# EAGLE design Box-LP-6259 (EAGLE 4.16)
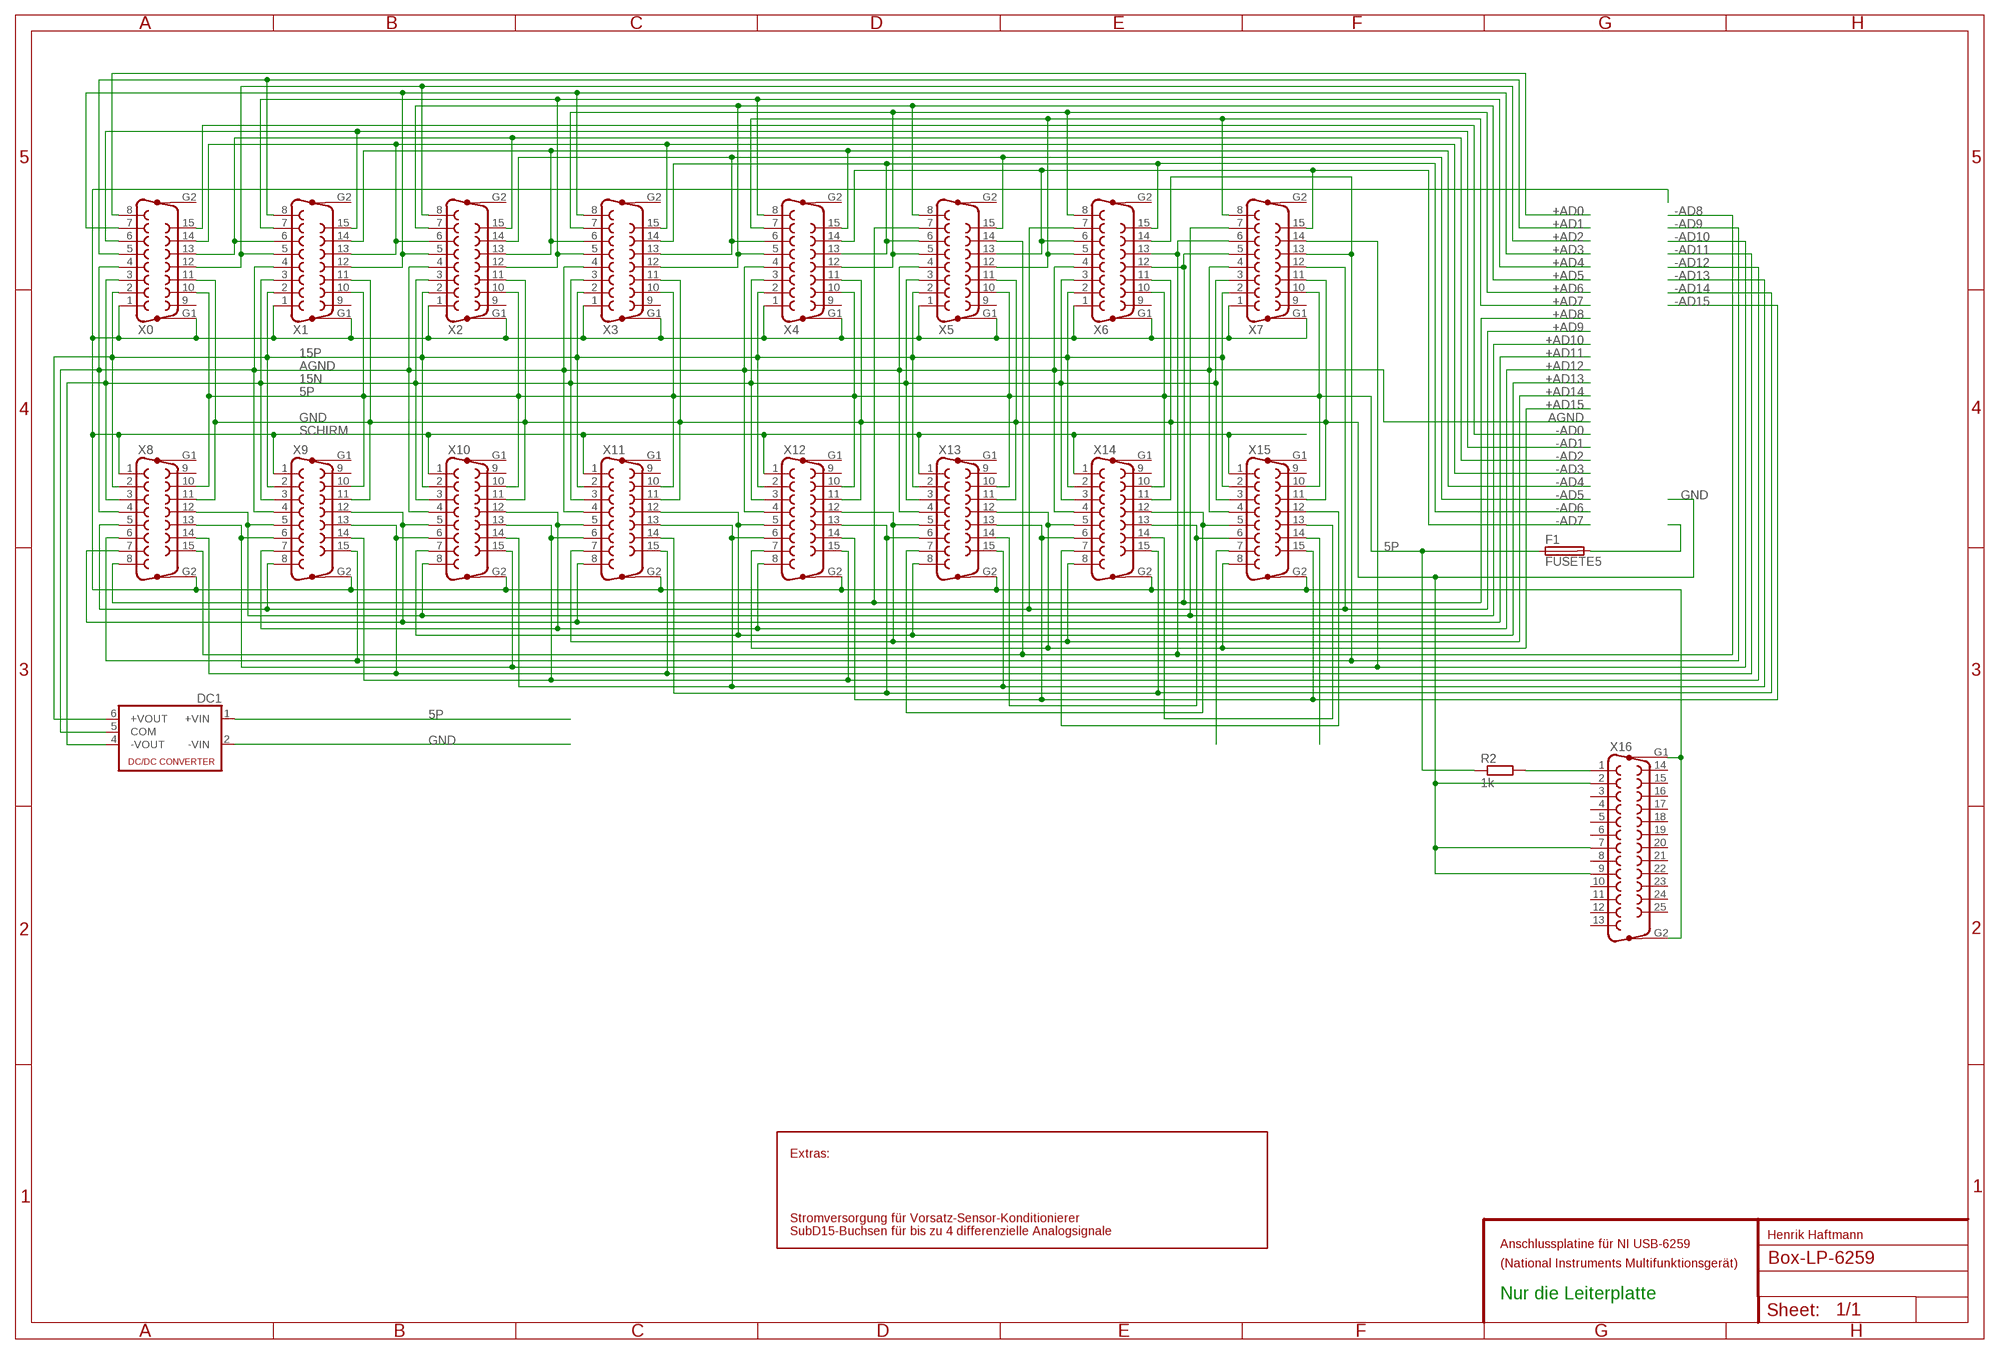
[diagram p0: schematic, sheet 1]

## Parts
DC1  NMA  [NMA]
F1  FUSETE5  [TE5]
R2  1k  R-EU_R0805  [R0805]
X0  F15VP  [F15VP]
X1  F15VP  [F15VP]
X2  F15VP  [F15VP]
X3  F15VP  [F15VP]
X4  F15VP  [F15VP]
X5  F15VP  [F15VP]
X6  F15VP  [F15VP]
X7  F15VP  [F15VP]
X8  F15VP  [F15VP]
X9  F15VP  [F15VP]
X10  F15VP  [F15VP]
X11  F15VP  [F15VP]
X12  F15VP  [F15VP]
X13  F15VP  [F15VP]
X14  F15VP  [F15VP]
X15  F15VP  [F15VP]
X16  F25VP  [F25VP]

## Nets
5P: DC1.1(+VIN) F1.1 R2.1 X0.10 X1.10 X2.10 X3.10 X4.10 X5.10 X6.10 X7.10 X8.10 X9.10 X10.10 X11.10 X12.10 X13.10 X14.10 X15.10
15N: DC1.4(-VOUT) X0.3 X1.3 X2.3 X3.3 X4.3 X5.3 X6.3 X7.3 X8.3 X9.3 X10.3 X11.3 X12.3 X13.3 X14.3 X15.3
15P: DC1.6(+VOUT) X0.2 X1.2 X2.2 X3.2 X4.2 X5.2 X6.2 X7.2 X8.2 X9.2 X10.2 X11.2 X12.2 X13.2 X14.2 X15.2
+AD0: X0.8
+AD1: X0.5 X1.8
+AD2: X0.12 X1.5 X2.8
+AD3: X0.7 X1.12 X2.5 X3.8
+AD4: X1.7 X2.12 X3.5 X4.8
+AD5: X2.7 X3.12 X4.5 X5.8
+AD6: X3.7 X4.12 X5.5 X6.8
+AD7: X4.7 X5.12 X6.5 X7.8
+AD8: X5.7 X6.12 X7.5 X8.8
+AD9: X6.7 X7.12 X8.5 X9.8
+AD10: X7.7 X8.12 X9.5 X10.8
+AD11: X8.7 X9.12 X10.5 X11.8
+AD12: X9.7 X10.12 X11.5 X12.8
+AD13: X10.7 X11.12 X12.5 X13.8
+AD14: X11.7 X12.12 X13.5 X14.8
+AD15: X12.7 X13.12 X14.5 X15.8
+AD16: X13.7 X14.12 X15.5
+AD17: X14.7 X15.12
+AD18: X15.7
-AD0: X0.15
-AD1: X0.6 X1.15
-AD2: X0.13 X1.6 X2.15
-AD3: X0.14 X1.13 X2.6 X3.15
-AD4: X1.14 X2.13 X3.6 X4.15
-AD5: X2.14 X3.13 X4.6 X5.15
-AD6: X3.14 X4.13 X5.6 X6.15
-AD7: X4.14 X5.13 X6.6 X7.15
-AD8: X5.14 X6.13 X7.6 X8.15
-AD9: X6.14 X7.13 X8.6 X9.15
-AD10: X7.14 X8.13 X9.6 X10.15
-AD11: X8.14 X9.13 X10.6 X11.15
-AD12: X9.14 X10.13 X11.6 X12.15
-AD13: X10.14 X11.13 X12.6 X13.15
-AD14: X11.14 X12.13 X13.6 X14.15
-AD15: X12.14 X13.13 X14.6 X15.15
-AD16: X13.14 X14.13 X15.6
-AD17: X14.14 X15.13
-AD18: X15.14
AGND: DC1.5(COM) X0.4 X1.4 X2.4 X3.4 X4.4 X5.4 X6.4 X7.4 X8.4 X9.4 X10.4 X11.4 X12.4 X13.4 X14.4 X15.4
GND: DC1.2(-VIN) X0.11 X1.11 X2.11 X3.11 X4.11 X5.11 X6.11 X7.11 X8.11 X9.11 X10.11 X11.11 X12.11 X13.11 X14.11 X15.11 X16.2 X16.7 X16.9
N$1: R2.2 X16.1
N$2: F1.2
SCHIRM: X0.1 X0.G1 X1.1 X1.G1 X2.1 X2.G1 X3.1 X3.G1 X4.1 X4.G1 X5.1 X5.G1 X6.1 X6.G1 X7.1 X7.G1 X8.1 X8.G2 X9.1 X9.G2 X10.1 X10.G2 X11.1 X11.G2 X12.1 X12.G2 X13.1 X13.G2 X14.1 X14.G2 X15.1 X15.G2 X16.G1 X16.G2
Unconnected: X0.9 X0.G2 X1.9 X1.G2 X2.9 X2.G2 X3.9 X3.G2 X4.9 X4.G2 X5.9 X5.G2 X6.9 X6.G2 X7.9 X7.G2 X8.9 X8.G1 X9.9 X9.G1 X10.9 X10.G1 X11.9 X11.G1 X12.9 X12.G1 X13.9 X13.G1 X14.9 X14.G1 X15.9 X15.G1 X16.3 X16.4 X16.5 X16.6 X16.8 X16.10 X16.11 X16.12 X16.13 X16.14 X16.15 X16.16 X16.17 X16.18 X16.19 X16.20 X16.21 X16.22 X16.23 X16.24 X16.25

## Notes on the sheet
- Extras:
- Stromversorgung für Vorsatz-Sensor-Konditionierer
- SubD15-Buchsen für bis zu 4 differenzielle Analogsignale
- Henrik Haftmann
- Anschlussplatine für NI USB-6259
- (National Instruments Multifunktionsgerät)
- Nur die Leiterplatte

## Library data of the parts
DC1 = dc-dc-converter:NMA: DC-DC CONVERTER
F1 = fuse:FUSE: Fuse
R2 = rcl:R-EU_: RESISTOR, European symbol
X0 X1-X15 = con-subd:F15VP: SUB-D
X16 = con-subd:F25VP: SUB-D

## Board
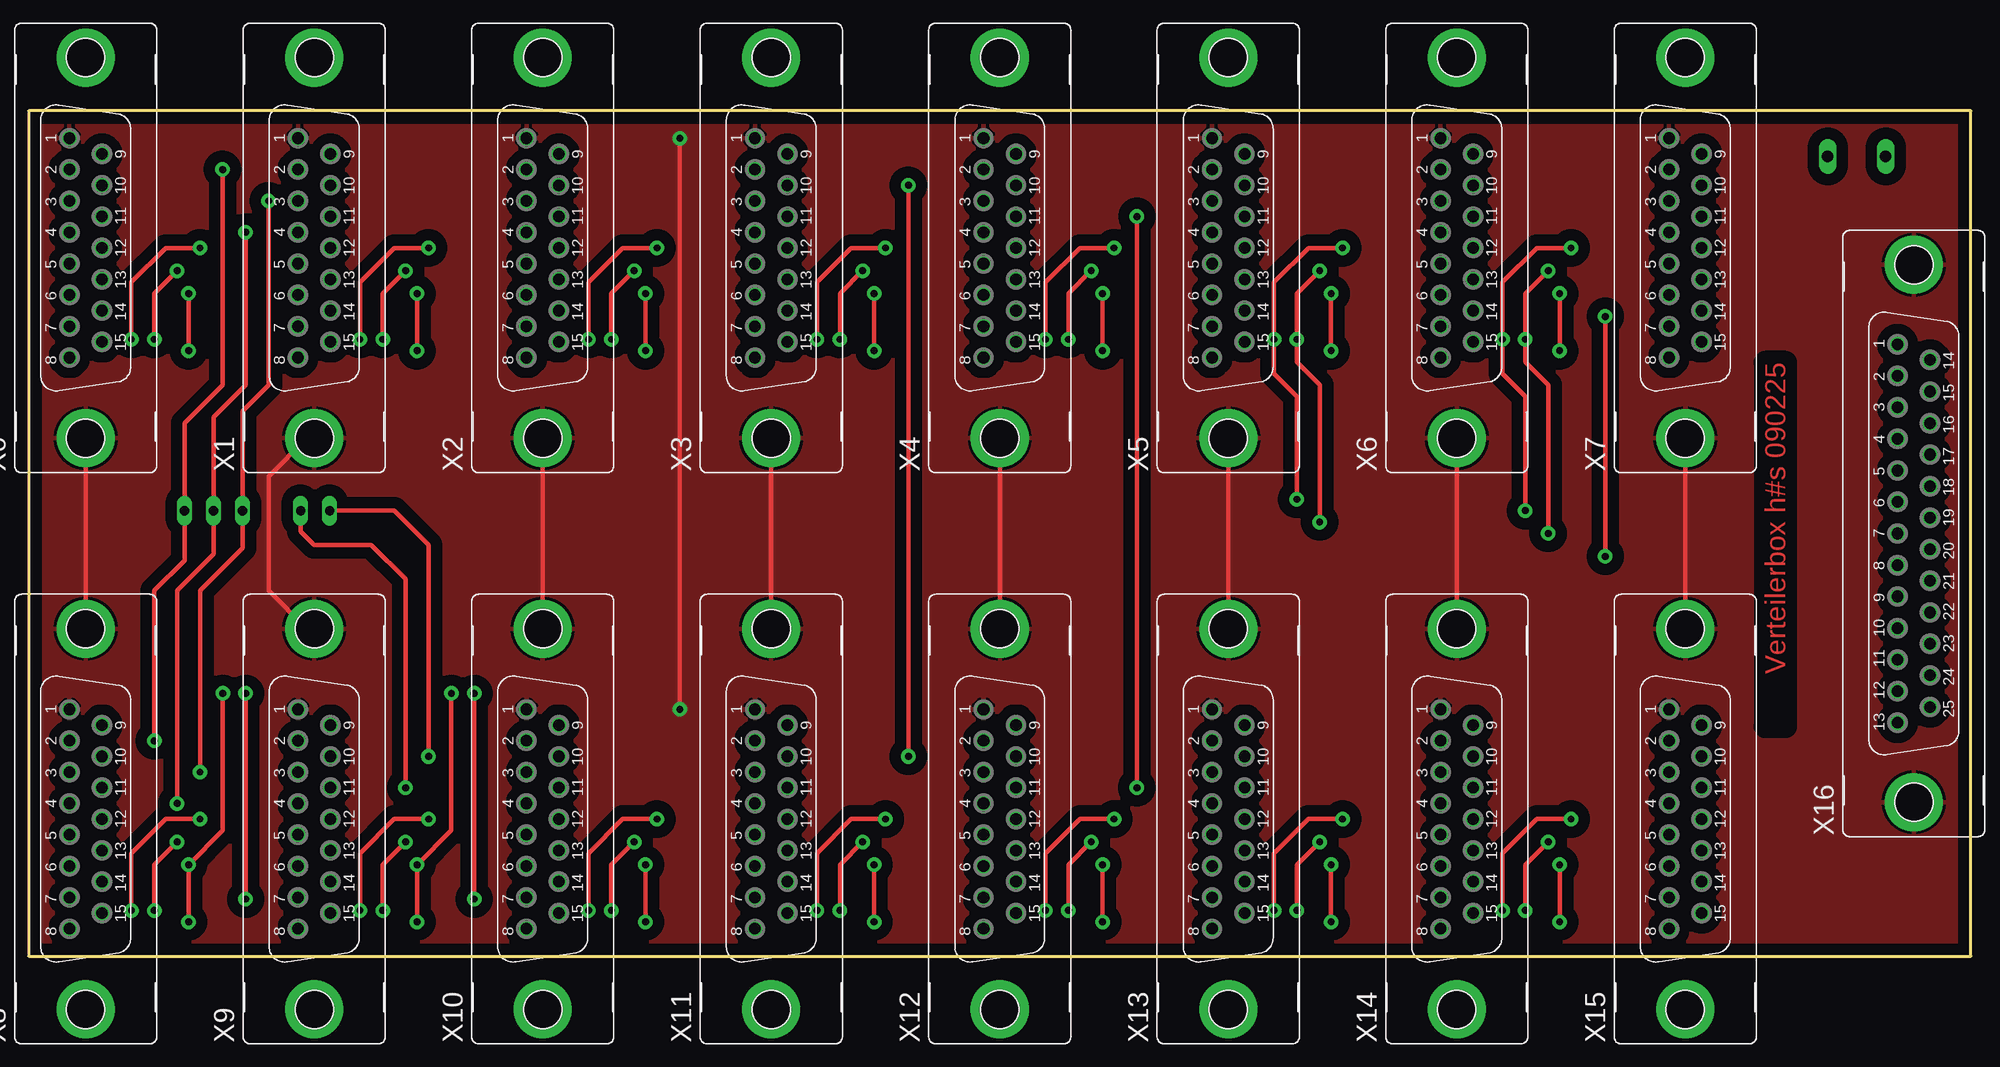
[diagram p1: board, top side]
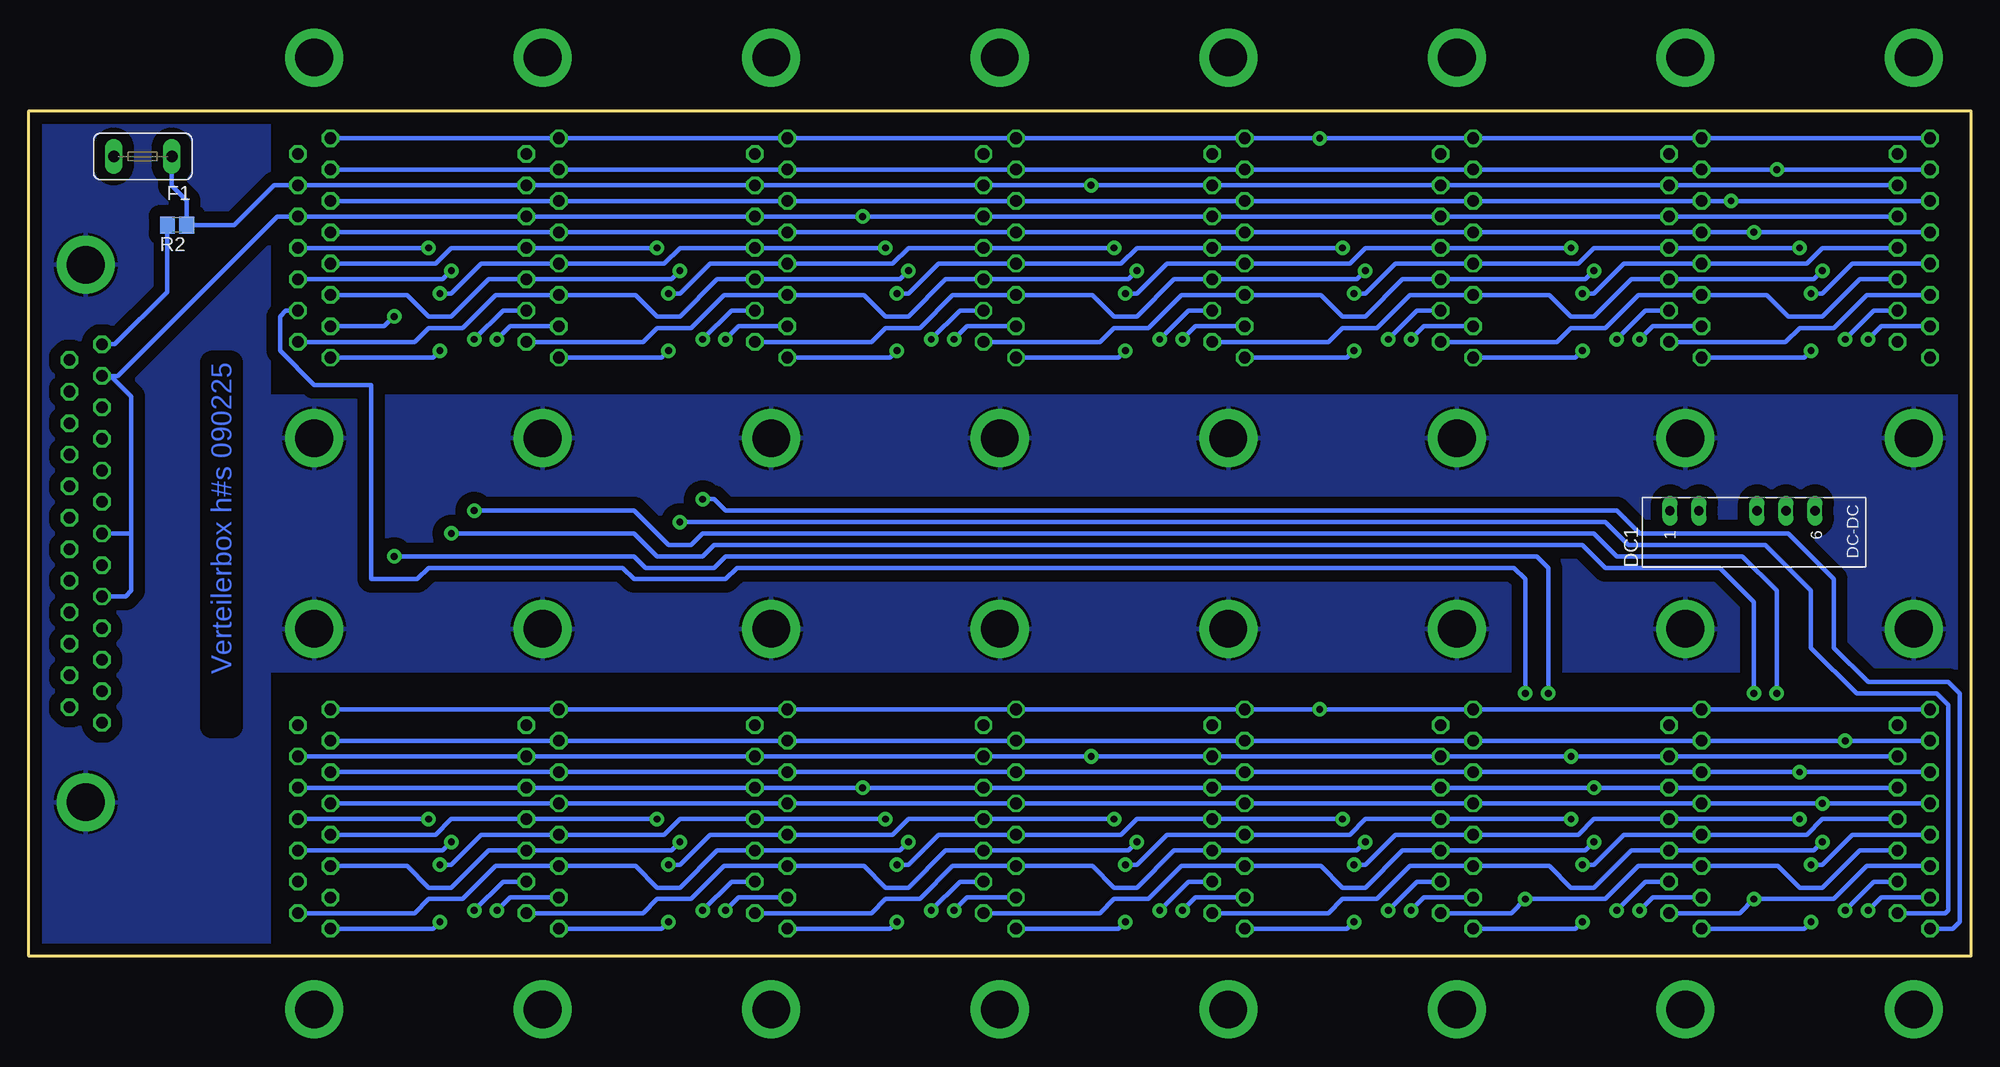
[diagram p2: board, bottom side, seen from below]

Size 170 x 74 mm. Coordinates in mm from the lower left corner, seen from the top.
Outline: 0,0 170,0 170,74 0,74 0,0
Copper layers (1*16): Top 0.035mm / dielectric 1.5mm / Bottom 0.035mm
Design rules "Felber": minimum track width 0.15mm, minimum drill 0.3mm, track to track 0.15mm, track to pad 0.15mm, pad to pad 0.15mm, via to via 0.15mm, smd to smd 0mil, copper to edge 0.3mm, drill to drill 0.3mm, minimum pad ring 10mil, minimum via ring 8mil, stop-mask expansion 4mil, vias tented up to drill 0mil, thermal gap 10mil

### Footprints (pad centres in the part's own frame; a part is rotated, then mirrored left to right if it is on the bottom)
NMA = drill 0.813 long: 1 0,6.35; 2 0,3.81; 4 0,-1.27; 5 0,-3.81; 6 0,-6.35
TE5 = drill 1.016 long: 1 -2.54,0; 2 2.54,0
R0805 = smd 1.3 x 1.5: 1 -0.85,0; 2 0.85,0
F15VP = drill 1.016 octagon: 1 9.601,1.422; 2 6.858,1.422; 3 4.115,1.422; 4 1.372,1.422; 5 -1.372,1.422; 6 -4.115,1.422; 7 -6.858,1.422; 8 -9.601,1.422; 9 8.23,-1.422; 10 5.486,-1.422; 11 2.743,-1.422; 12 0,-1.422; 13 -2.743,-1.422; 14 -5.486,-1.422; 15 -8.23,-1.422 | drill 3.302 pad 5.08 round: G1 -16.662,0; G2 16.662,0
F25VP = drill 1.016 octagon: 1 16.561,1.422; 2 13.792,1.422; 3 11.049,1.422; 4 8.28,1.422; 5 5.512,1.422; 6 2.769,1.422; 7 0,1.422; 8 -2.769,1.422; 9 -5.512,1.422; 10 -8.28,1.422; 11 -11.049,1.422; 12 -13.792,1.422; 13 -16.561,1.422; 14 15.189,-1.422; 15 12.421,-1.422; 16 9.652,-1.422; 17 6.909,-1.422; 18 4.14,-1.422; 19 1.372,-1.422; 20 -1.372,-1.422; 21 -4.14,-1.422; 22 -6.909,-1.422; 23 -9.652,-1.422; 24 -12.421,-1.422; 25 -15.189,-1.422 | drill 3.302 pad 5.08 round: G1 -23.52,0; G2 23.52,0

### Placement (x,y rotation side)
DC1  20,39 90 bottom
F1  160,70 180 bottom
R2  157,64 180 bottom
X0  5,62 90 top
X1  25,62 90 top
X2  45,62 90 top
X3  65,62 90 top
X4  85,62 90 top
X5  105,62 90 top
X6  125,62 90 top
X7  145,62 90 top
X8  5,12 90 top
X9  25,12 90 top
X10  45,12 90 top
X11  65,12 90 top
X12  85,12 90 top
X13  105,12 90 top
X14  125,12 90 top
X15  145,12 90 top
X16  165,37 90 top

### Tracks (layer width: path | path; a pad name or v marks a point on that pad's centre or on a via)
5P  (via drill 0.6 pad 1.27)
  Top 0.406: 77,36 v77,67.49 | 77,36 | v77,17.49 77,36 | DC1.1 32,39 35,36 v35,17.49
  Bottom 0.406: X0.10 X1.10 X2.10 X3.10 v77,67.49 X4.10 X5.10 X6.10 X7.10 148.51,67.49 152,64 R2.1 156.15,66.15 157.46,67.46 F1.1 | X8.10 X9.10 v35,17.49 X10.10 X11.10 v77,17.49 X12.10 X13.10 X14.10 X15.10
15N  (via drill 0.6 pad 1.27)
  Top 0.406: v21,66.11 21,50 18.73,47.73 DC1.4 18.73,35.73 15,32 v15,16.11
  Bottom 0.406: X0.3 v21,66.11 X1.3 X2.3 X3.3 X4.3 X5.3 X6.3 X7.3 | X8.3 v15,16.11 X9.3 X10.3 X11.3 X12.3 X13.3 X14.3 X15.3
15P  (via drill 0.6 pad 1.27)
  Top 0.406: v11,18.86 11,32 13.65,34.65 DC1.6 13.65,46.65 17,50 16.98,50.02 v16.98,68.86
  Bottom 0.406: X0.2 v16.98,68.86 X1.2 X2.2 X3.2 X4.2 X5.2 X6.2 X7.2 | X8.2 v11,18.86 X9.2 X10.2 X11.2 X12.2 X13.2 X14.2 X15.2
+AD1  (via drill 0.6 pad 1.27)
  Top 0.406: v14,58 v14,53
  Bottom 0.406: X0.5 10.37,60.63 13,58 v14,58 | X1.8 14.6,52.4 v14,53
+AD2  (via drill 0.6 pad 1.27)
  Top 0.406: v34,58 v34,53
  Bottom 0.406: X0.12 13,62 14.37,60.63 X1.5 30.37,60.63 33,58 v34,58 | X2.8 34.6,52.4 v34,53
+AD3  (via drill 0.6 pad 1.27)
  Top 0.406: v54,58 v54,53 | v9,54 9,59 12,62 v15,62
  Bottom 0.406: v54,58 53,58 50.37,60.63 X2.5 34.37,60.63 33,62 X1.12 v15,62 | X3.8 54.6,52.4 v54,53 | X0.7 7.86,55.14 v9,54
+AD4  (via drill 0.6 pad 1.27)
  Top 0.406: v74,58 v74,53 | v29,54 29,59 32,62 v35,62
  Bottom 0.406: v74,58 73,58 70.37,60.63 X3.5 54.37,60.63 53,62 X2.12 v35,62 | X4.8 74.6,52.4 v74,53 | X1.7 27.86,55.14 v29,54
+AD5  (via drill 0.6 pad 1.27)
  Top 0.406: v94,58 v94,53 | v55,62 52,62 49,59 v49,54
  Bottom 0.406: v94,58 93,58 90.37,60.63 X4.5 74.37,60.63 73,62 X3.12 v55,62 | X5.8 94.6,52.4 v94,53 | X2.7 47.86,55.14 v49,54
+AD6  (via drill 0.6 pad 1.27)
  Top 0.406: v114,58 v114,53 | v69,54 69,59 72,62 v75,62
  Bottom 0.406: v114,58 113,58 110.37,60.63 X5.5 94.37,60.63 93,62 X4.12 v75,62 | X6.8 114.6,52.4 v114,53 | X3.7 67.86,55.14 v69,54
+AD7  (via drill 0.6 pad 1.27)
  Top 0.406: v134,58 v134,53 | v89,54 89,59 92,62 v95,62
  Bottom 0.406: v134,58 133,58 130.37,60.63 X6.5 114.37,60.63 113,62 X5.12 v95,62 | X7.8 134.6,52.4 v134,53 | X4.7 87.86,55.14 v89,54
+AD8  (via drill 0.6 pad 1.27)
  Top 0.406: v115,62 112,62 109,59 v109,54 109,51 111,49 v111,40
  Bottom 0.406: X7.5 134.37,60.63 133,62 X6.12 v115,62 | X8.8 1.6,2.4 1,3 1,23 2,24 9,24 12,27 12,33 16,37 29,37 31,39 109,39 110,40 v111,40 | X5.7 107.86,55.14 v109,54
+AD9  (via drill 0.6 pad 1.27)
  Top 0.406: v14,3 v14,8 17,11 v17,23 | v131,39 131,49 129,51 v129,54 129,59 132,62 v135,62
  Bottom 0.406: X8.5 10.37,10.63 13,8 v14,8 | X9.8 14.6,2.4 v14,3 | v17,23 17,32 20,35 31,35 33,37 111,37 112,36 114,36 117,39 v131,39 | X6.7 127.86,55.14 v129,54 | v135,62 X7.12
+AD10  (via drill 0.6 pad 1.27)
  Top 0.406: v34,3 v34,8 37,11 v37,23 | v138,35 v138,56
  Bottom 0.406: v34,8 33,8 30.37,10.63 X9.5 14.37,10.63 13,12 X8.12 | X10.8 34.6,2.4 v34,3 | X7.7 138.86,55.14 v138,56 | v138,35 117,35 116,34 110,34 109,35 38,35 37,34 v37,23
+AD11  (via drill 0.6 pad 1.27)
  Top 0.406: v54,8 v54,3 | v9,4 9,9 12,12 v15,12
  Bottom 0.406: v54,8 53,8 50.37,10.63 X10.5 34.37,10.63 33,12 X9.12 v15,12 | X11.8 54.6,2.4 v54,3 | X8.7 7.86,5.14 v9,4
+AD12  (via drill 0.6 pad 1.27)
  Top 0.406: v74,8 v74,3 | v29,4 29,9 32,12 v35,12
  Bottom 0.406: v74,8 73,8 70.37,10.63 X11.5 54.37,10.63 53,12 X10.12 v35,12 | X12.8 74.6,2.4 v74,3 | X9.7 27.86,5.14 v29,4
+AD13  (via drill 0.6 pad 1.27)
  Top 0.406: v94,8 v94,3 | v49,4 49,9 52,12 v55,12
  Bottom 0.406: v94,8 93,8 90.37,10.63 X12.5 74.37,10.63 73,12 X11.12 v55,12 | X13.8 94.6,2.4 v94,3 | X10.7 47.86,5.14 v49,4
+AD14  (via drill 0.6 pad 1.27)
  Top 0.406: v114,8 v114,3 | v69,4 69,9 72,12 v75,12
  Bottom 0.406: v114,8 113,8 110.37,10.63 X13.5 94.37,10.63 93,12 X12.12 v75,12 | X14.8 114.6,2.4 v114,3 | X11.7 67.86,5.14 v69,4
+AD15  (via drill 0.6 pad 1.27)
  Top 0.406: v134,8 v134,3 | v89,4 89,9 92,12 v95,12
  Bottom 0.406: v134,8 133,8 130.37,10.63 X14.5 114.37,10.63 113,12 X13.12 v95,12 | X15.8 134.6,2.4 v134,3 | X12.7 87.86,5.14 v89,4
+AD16  (via drill 0.6 pad 1.27)
  Top 0.406: v109,4 109,9 112,12 v115,12
  Bottom 0.406: X13.7 107.86,5.14 v109,4 | v115,12 X14.12 133,12 134.37,10.63 X15.5
+AD17  (via drill 0.6 pad 1.27)
  Top 0.406: v129,4 129,9 132,12 v135,12
  Bottom 0.406: X14.7 127.86,5.14 v129,4 | v135,12 X15.12
-AD1
  Bottom 0.406: X0.6 9.12,57.89 12,55 15,55 16.23,53.77 X1.15
-AD2
  Bottom 0.406: X0.13 9.74,59.26 13,56 16,56 17.89,57.89 X1.6 29.11,57.89 32,55 35,55 36.23,53.77 X2.15
-AD3  (via drill 0.6 pad 1.27)
  Top 0.406: v11,54 11,58 v13,60
  Bottom 0.406: X3.15 56.23,53.77 55,55 52,55 49.12,57.89 X2.6 36.88,57.89 35,56 33,56 29.74,59.26 X1.13 22.26,59.26 13.74,59.26 v13,60 | X0.14 8.49,56.51 v11,54
-AD4  (via drill 0.6 pad 1.27)
  Top 0.406: v31,54 31,58 v33,60
  Bottom 0.406: X4.15 76.23,53.77 75,55 72,55 69.11,57.89 X3.6 56.88,57.89 55,56 53,56 49.74,59.26 X2.13 33.74,59.26 v33,60 | X1.14 28.49,56.51 v31,54
-AD5  (via drill 0.6 pad 1.27)
  Top 0.406: v51,54 51,58 v53,60
  Bottom 0.406: X5.15 96.23,53.77 95,55 92,55 89.11,57.89 X4.6 76.89,57.89 75,56 73,56 69.74,59.26 X3.13 53.74,59.26 v53,60 | X2.14 48.49,56.51 v51,54
-AD6  (via drill 0.6 pad 1.27)
  Top 0.406: v71,54 71,58 v73,60
  Bottom 0.406: X6.15 116.23,53.77 115,55 112,55 109.11,57.89 X5.6 96.89,57.89 95,56 93,56 89.74,59.26 X4.13 73.74,59.26 v73,60 | X3.14 68.49,56.51 v71,54
-AD7  (via drill 0.6 pad 1.27)
  Top 0.406: v91,54 91,58 v93,60
  Bottom 0.406: X7.15 136.23,53.77 135,55 132,55 129.12,57.89 X6.6 116.89,57.89 115,56 113,56 109.74,59.26 X5.13 93.74,59.26 v93,60 | X4.14 88.49,56.51 v91,54
-AD8  (via drill 0.6 pad 1.27)
  Top 0.406: v113,60 111,58 v111,54 111,52 113,50 v113,38
  Bottom 0.406: X7.6 136.88,57.89 135,56 133,56 129.74,59.26 X6.13 113.74,59.26 v113,60 | X8.15 2.23,3.77 2,4 2,22 3,23 10,23 14,27 14,32 18,36 30,36 32,38 v113,38 | X5.14 108.49,56.51 v111,54
-AD9  (via drill 0.6 pad 1.27)
  Top 0.406: v133,37 133,50 131,52 v131,54 131,58 v133,60 | v19,5 v19,23
  Bottom 0.406: X8.6 9.12,7.88 12,5 v19,5 20.23,3.77 X9.15 | v19,23 19,31 22,34 32,34 34,36 110,36 111,35 115,35 117,37 v133,37 | X6.14 128.49,56.51 v131,54 | X7.13 133.74,59.26 v133,60
-AD10  (via drill 0.6 pad 1.27)
  Top 0.406: v39,5 v39,23
  Bottom 0.406: X8.13 9.74,9.26 13,6 15,6 16.89,7.88 X9.6 29.11,7.88 32,5 v39,5 40.23,3.77 X10.15 | X7.14 147.49,56.51 148,56 148,53 145,50 140,50 140,33 136,33 135,34 118,34 117,33 109,33 108,34 40,34 39,33 v39,23
-AD11  (via drill 0.6 pad 1.27)
  Top 0.406: v11,4 11,8 v13,10
  Bottom 0.406: X11.15 56.23,3.77 55,5 52,5 49.12,7.88 X10.6 36.88,7.88 35,6 33,6 29.74,9.26 X9.13 13.74,9.26 v13,10 | X8.14 8.49,6.51 v11,4
-AD12  (via drill 0.6 pad 1.27)
  Top 0.406: v31,4 31,8 v33,10
  Bottom 0.406: X12.15 76.23,3.77 75,5 72,5 69.11,7.88 X11.6 56.88,7.88 55,6 53,6 49.74,9.26 X10.13 33.74,9.26 v33,10 | X9.14 28.49,6.51 v31,4
-AD13  (via drill 0.6 pad 1.27)
  Top 0.406: v51,4 51,8 v53,10
  Bottom 0.406: X13.15 96.23,3.77 95,5 92,5 89.11,7.88 X12.6 76.89,7.88 75,6 73,6 69.74,9.26 X11.13 53.74,9.26 v53,10 | X10.14 48.49,6.51 v51,4
-AD14  (via drill 0.6 pad 1.27)
  Top 0.406: v71,4 71,8 v73,10
  Bottom 0.406: X14.15 116.23,3.77 115,5 112,5 109.11,7.88 X13.6 96.89,7.88 95,6 93,6 89.74,9.26 X12.13 73.74,9.26 v73,10 | X11.14 68.49,6.51 v71,4
-AD15  (via drill 0.6 pad 1.27)
  Top 0.406: v91,4 91,8 v93,10
  Bottom 0.406: X15.15 136.23,3.77 135,5 132,5 129.12,7.88 X14.6 116.89,7.88 115,6 113,6 109.74,9.26 X13.13 93.74,9.26 v93,10 | X12.14 88.49,6.51 v91,4
-AD16  (via drill 0.6 pad 1.27)
  Top 0.406: v111,4 111,8 v113,10
  Bottom 0.406: X13.14 108.49,6.51 v111,4 | v113,10 113.74,9.26 X14.13 129.74,9.26 133,6 135,6 136.88,7.88 X15.6
-AD17  (via drill 0.6 pad 1.27)
  Top 0.406: v131,4 131,8 v133,10
  Bottom 0.406: X14.14 128.49,6.51 v131,4 | X15.13 133.74,9.26 v133,10
AGND  (via drill 0.6 pad 1.27)
  Top 0.406: v19,63.37 19,50 16.19,47.19 DC1.5 16.19,35.19 13,32 v13,13.37
  Bottom 0.406: X0.4 v19,63.37 X1.4 X2.4 X3.4 X4.4 X5.4 X6.4 X7.4 | X8.4 v13,13.37 X9.4 X10.4 X11.4 X12.4 X13.4 X14.4 X15.4
GND  (via drill 0.6 pad 1.27)
  Top 0.406: v97.01,64.74 97.01,36.01 97,36 v97,14.74 | DC1.2 23.81,37.19 25,36 30,36 33,33 v33,14.74
  Bottom 0.406: X0.11 X1.11 X2.11 X3.11 X4.11 v97.01,64.74 X5.11 X6.11 X7.11 148.26,64.74 162.21,50.79 X16.2 162.79,50.79 161,49 161,37 | X8.11 X9.11 v33,14.74 X10.11 X11.11 X12.11 v97,14.74 X13.11 X14.11 X15.11 | X16.9 161.51,31.49 161,32 161,37 | 161,37 X16.7
N$1
  Bottom 0.406: X16.1 162.44,53.56 157.85,58.15 R2.2
SCHIRM  (via drill 0.6 pad 1.27)
  Top 0.406: X10.G2 X2.G1 | X1.G1 24.34,45.34 21,42 21,32 24.34,28.66 X9.G2 | X8.G2 X0.G1 | X11.G2 X3.G1 | X12.G2 X4.G1 | X13.G2 X5.G1 | X14.G2 X6.G1 | X15.G2 X7.G1 | v57,21.6 57,71 v57,71.6
  Bottom 0.406: X0.1 X1.1 X2.1 v57,71.6 X3.1 X4.1 X5.1 X6.1 X7.1 | X8.1 X9.1 X10.1 v57,21.6 X11.1 X12.1 X13.1 X14.1 X15.1
  pour Top (isolate 1): 1,73 169,73 169,1 1,1
  pour Bottom (isolate 1): 1,49 149,49 149,73 169,73 169,1 149,1 149,25 1,25

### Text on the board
Top: Verteilerbox h#s 090225
Bottom: Verteilerbox h#s 090225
